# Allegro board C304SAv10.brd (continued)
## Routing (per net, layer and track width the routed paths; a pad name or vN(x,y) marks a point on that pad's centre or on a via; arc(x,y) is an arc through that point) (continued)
27M_FPGA: length 25.1
  TOP w0.15: D9.Y28 v1(34,99) ; R69.2 v1(17.9,108.5)
  BOTTOM w0.15: v1(17.9,108.5) 20.1,106.3 31.9,106.3 34,104.2 v1(34,99)
706MR: length 84
  TOP w0.2: 84.45,56.75 D3.1 82.45,56.75 X3.1 82.45,60.75 R11.1 v3(83.95,61.95) ; D1.74 68.45,105.45 69.95,103.95 v2(70,103.95)
  BOTTOM w0.2: R11.1 v3(83.95,61.95) 83.95,62.95 86.25,65.25 90.05,65.25 90.6,65.8 90.6,71 90.1,71.5 90.1,97.2 83.35,103.95 v2(70,103.95)
706WDI: length 80.7
  TOP w0.2: v2(68.35,104.55) 67.95,104.95 D1.73 ; D3.6 v3(91.71,54.21)
  BOTTOM w0.2: v2(68.35,104.55) 85.95,104.55 92.8,97.7 92.8,55.3 v3(91.71,54.21)
ASI_OUTN1: length 40.8
  TOP w0.2: D9.D1 17.5,70.7 17.4,70.6 17.4,68.4 v2(16.5,67.5) ; v3(8.75,38.1) R76.2
  TOP w0.3: C150.1 8.9,36.65 R76.2
  MIDLAYER w0.2: v3(8.75,38.1) 9.8,39.15 9.8,58.87 16.7,65.77 16.7,67.3 v2(16.5,67.5)
ASI_OUTN2: length 40
  TOP w0.2: D9.G1 20.5,69.61 20.45,69.56 20.45,66.45 v2(19.9,65.9) ; v3(24.75,38.1) R93.2
  TOP w0.3: R93.2 24.9,36.65 C162.1
  MIDLAYER w0.2: v2(19.9,65.9) 20.1,65.9 23.35,62.65 23.35,42.25 25.6,40 25.6,38.95 v3(24.75,38.1)
ASI_OUTN3: length 41.2
  TOP w0.2: D9.W1 32.5,70.86 32.85,70.51 32.85,64.05 v2(32.4,63.6) ; R101.2 40.7,36.85 v3(40.7,38.1)
  TOP w0.3: C170.1 40.9,36.65 R101.2
  MIDLAYER w0.2: v3(40.7,38.1) 41.27,38.67 41.27,38.97 32.7,47.53 32.7,63.3 v2(32.4,63.6)
ASI_OUTN4: length 52.8
  TOP w0.2: D9.AC1 36.5,70.51 36.45,70.46 36.45,67.05 v2(35.9,66.5) ; R109.2 v3(56.75,38.1)
  TOP w0.3: C178.1 56.9,36.65 R109.2
  MIDLAYER w0.2: v2(35.9,66.5) 45.5,66.5 57.75,54.25 57.75,38.3 57.55,38.1 v3(56.75,38.1)
ASI_OUTP1: length 41.8
  TOP w0.2: v3(11.15,38.1) R76.1 ; D9.D2 17,72 17,68.8 v2(16.6,68.4)
  TOP w0.3: C149.1 11,36.65 R76.1
  MIDLAYER w0.2: v3(11.15,38.1) 10.2,39.05 10.2,58.7 17.1,65.6 17.1,67.9 v2(16.6,68.4)
ASI_OUTP2: length 41.3
  TOP w0.2: v2(19.9,66.7) 20.05,66.85 20.05,69.56 20,69.61 20,72 D9.G2 ; v3(27.15,38.1) R93.1
  TOP w0.3: R93.1 27,36.65 C161.1
  MIDLAYER w0.2: v2(19.9,66.7) 23.75,62.85 23.75,42.45 26,40.2 26,39.25 v3(27.15,38.1)
ASI_OUTP3: length 43.1
  TOP w0.2: D9.W2 32,72 32,70.7 32.45,70.25 32.45,64.75 32.3,64.6 v2(32.3,64.5) ; R101.1 43.1,36.85 v3(43.1,38.1)
  TOP w0.3: C169.1 43,36.65 R101.1
  MIDLAYER w0.2: v3(43.1,38.1) 42.7,38.1 33.1,47.7 33.1,63.7 v2(32.3,64.5)
ASI_OUTP4: length 53.8
  TOP w0.2: v2(35.9,67.3) 35.9,67.4 36.05,67.55 36.05,70.46 36,70.51 36,72 D9.AC2 ; R109.1 v3(59.15,38.1)
  TOP w0.3: R109.1 59,36.65 C177.1
  MIDLAYER w0.2: v2(35.9,67.3) 36.3,66.9 45.67,66.9 58.15,54.42 58.15,38.3 58.35,38.1 v3(59.15,38.1)
AT91_CAS: length 54.7
  TOP w0.2: v2(71.9,170.65) D5.17 82.25,170.65 82.75,170.15 82.75,157.25 73.45,147.95 D1.177 ; D6.17 v2(61.35,170.65)
  BOTTOM w0.2: v2(71.9,170.65) v2(61.35,170.65) 61.25,170.65
AT91_NCS0: length 53.4
  TOP w0.2: D1.166 78.95,145.95 v2(79.45,146.45) ; v2(74.8,187.9) 74.8,189.9 74.2,190.5 D7.26 72.85,190.5
  MIDLAYER w0.2: v2(79.45,146.45) 80.25,147.25 80.25,184.35 76.7,187.9 v2(74.8,187.9)
AT91_NCS1: length 51.4
  TOP w0.2: D5.19 v2(78.7,172.25) ; D1.167 78.45,149.55 v2(78.7,149.8) ; D6.19 v2(61.25,172.25)
  BOTTOM w0.2: v2(61.25,172.25) v2(78.7,172.25) 77.3,170.85 77.3,157.1 78.7,155.7 v2(78.7,149.8)
AT91_NCS7: length 64.2
  TOP w0.15: v2(49.5,109.4) 49.5,99.6 46.9,97 41,97 D9.AG26
  TOP w0.2: D1.14 v2(56.85,133.75)
  BOTTOM w0.2: v2(49.5,109.4) 59.9,109.4 64.6,114.1 64.6,131 61.85,133.75 v2(56.85,133.75)
AT91_NRD: length 144.2
  TOP w0.15: v2(51.2,81.6) 51.1,81.5 D9.AH11
  TOP w0.2: D7.28 74.8,191.5 75.5,190.8 v2(75.5,187.1) ; v2(76.95,140.65) D1.170 76.95,145.15 v2(77.2,145.4)
  MIDLAYER w0.2: v2(51.2,81.6) 65.4,81.6 69,85.2 69,100.4 76.1,107.5 76.1,139.8 v2(76.95,140.65) ; v2(77.2,145.4) 79.85,148.05 79.85,183.75 76.5,187.1 v2(75.5,187.1)
AT91_NWE: length 167.4
  TOP w0.15: v2(52.9,82.6) 51.3,82.6 50.7,82 41,82 D9.AG12
  TOP w0.2: D7.11 56.05,196.5 v2(56.15,196.4) ; v2(77.45,146.75) 76.45,145.75 D1.171 76.45,141.35 v2(76.1,141)
  MIDLAYER w0.2: v2(76.1,141) 75.3,140.2 75.3,108 67.6,100.3 67.6,85.2 65,82.6 v2(52.9,82.6) ; v2(56.15,196.4) 56.15,188.65 58.4,186.4 76.2,186.4 79.45,183.15 79.45,148.75 v2(77.45,146.75)
AT91_RAS: length 58.7
  TOP w0.2: v2(72.9,171.45) D5.18 82.35,171.45 83.15,170.65 83.15,156.95 73.95,147.75 D1.176 ; D6.18 v2(58.15,171.45)
  BOTTOM w0.2: v2(58.15,171.45) v2(72.9,171.45)
AT91_SDCKE: length 68
  TOP w0.2: D1.175 74.45,147.4 v2(77.33,150.28) ; v2(73.15,168.45) 70.15,171.45 D5.37 66.75,171.45 62.75,175.45 62.75,178.75 62.05,179.45 56.55,179.45 55.25,178.15 55.25,174.25 52.45,171.45 D6.37
  BOTTOM w0.2: v2(73.15,168.45) 74.75,166.85 74.75,152.85 75.64,151.96 75.65,151.96 ; 77.32,150.28 75.65,151.95 75.65,151.96 ; 75.65,151.96 v2(77.33,150.28)
AT91_SDCLK: length 45.9
  TOP w0.2: D1.174 74.95,146.85 v2(76.15,148.05) ; v2(65.35,167.15) 65.35,168.35 R35.2
  BOTTOM w0.2: v2(76.15,148.05) 65.35,158.85 v2(65.35,167.15) 56.85,167.15 53.35,170.65 R36.2
AT91_SDWE: length 56.6
  TOP w0.2: D1.178 72.95,148.15 82.35,157.55 82.35,169.45 81.95,169.85 D5.16 v2(72.9,169.85) ; D6.16 v2(58.15,169.85)
  BOTTOM w0.2: v2(58.15,169.85) v2(72.9,169.85)
AT91A0: length 48.2
  TOP w0.2: D1.133 v2(88.85,128.75) ; D5.15 v2(81.75,169.05)
  BOTTOM w0.2: v2(88.85,128.75) 89.35,129.25 89.35,161.45 v2(81.75,169.05)
AT91A1: length 204.9
  TOP w0.15: D9.W27 33,98 33,107.9 30.3,110.6 30.3,167 46.6,183.3 v2(55.05,183.3)
  TOP w0.2: v2(71.6,185.5) 71.6,189.6 72,190 D7.25 ; D6.15 v2(61.25,169.05) ; v2(83.55,129.85) 84.15,129.25 D1.134
  MIDLAYER w0.2: v2(61.25,169.05) 59.65,170.65 57.35,170.65 55.05,172.95 v2(55.05,183.3) 55.05,184.85 55.7,185.5 v2(71.6,185.5)
  BOTTOM w0.2: v2(61.25,169.05) 74.55,169.05 76.05,167.55 76.05,154.65 78,152.7 78,135.4 v2(83.55,129.85)
AT91A2: length 218.3
  TOP w0.15: D9.AC27 37,98 37,107 32.3,111.7 32.3,165.8 46.15,179.65 v2(50.35,179.65)
  TOP w0.2: D5.23 v2(81.75,175.45) ; D6.23 v2(61.25,175.45) ; D7.24 54.9,190 55.65,189.25 v2(55.65,184.35) ; v2(89.15,180.54) 89.55,180.14 89.55,150.91 92.75,147.71 92.75,133.05 89.45,129.75 D1.135
  MIDLAYER w0.2: v2(55.65,184.35) 55.65,176.55 56.75,175.45 v2(61.25,175.45)
  BOTTOM w0.2: v2(50.35,179.65) 51.85,179.65 56.05,175.45 v2(61.25,175.45) v2(81.75,175.45) 84.05,175.45 89.14,180.54 v2(89.15,180.54)
AT91A3: length 213.3
  TOP w0.15: D9.AC28 36.5,106.8 31.8,111.5 31.8,166.1 46.05,180.35 v2(48.85,180.35)
  TOP w0.2: v2(56.25,183.25) 56.25,189.55 55.3,190.5 D7.23 ; D1.136 89.35,130.25 92.35,133.25 92.35,147.54 89.15,150.74 89.15,179.65 87.95,180.85 v2(87.93,180.85) ; D6.24 v2(58.15,176.25) ; D5.24 v2(78.65,176.25)
  MIDLAYER w0.2: v2(58.15,176.25) 57.05,176.25 56.25,177.05 v2(56.25,183.25)
  BOTTOM w0.2: v2(87.93,180.85) 87.93,180.83 83.35,176.25 v2(78.65,176.25) v2(58.15,176.25) 55.98,176.25 51.88,180.35 v2(48.85,180.35)
AT91A4: length 216.9
  TOP w0.15: D9.AB27 36,98 36,106.6 31.3,111.3 31.3,166.4 45.98,181.08 v2(50.3,181.08)
  TOP w0.2: D6.25 v2(61.25,177.05) ; D1.137 89.25,130.75 91.95,133.45 91.95,147.38 88.75,150.58 88.75,179.18 v2(86.76,181.16) ; v2(57.45,184.25) 57.45,189.25 55.7,191 D7.22 ; D5.25 v2(81.75,177.05)
  MIDLAYER w0.2: v2(57.45,184.25) 57.45,177.25 57.65,177.05 v2(61.25,177.05)
  BOTTOM w0.2: v2(50.3,181.08) 51.72,181.08 56.15,176.65 57.55,176.65 57.95,177.05 v2(61.25,177.05) v2(81.75,177.05) 82.65,177.05 v2(86.76,181.16)
AT91A5: length 212
  TOP w0.15: D9.AB28 35.5,106.4 30.8,111.1 30.8,166.7 45.82,181.72 v2(48.92,181.72)
  TOP w0.2: D5.26 v2(78.65,177.85) ; D1.138 89.15,131.25 91.55,133.65 91.55,147.21 88.35,150.41 88.35,178.73 v2(85.54,181.54) ; v2(58.15,183.25) 58.15,189.45 56.1,191.5 D7.21 ; D6.26 v2(58.15,177.85)
  MIDLAYER w0.2: v2(58.15,177.85) v2(58.15,183.25)
  BOTTOM w0.2: v2(48.92,181.72) 51.88,181.72 56.35,177.25 57.55,177.25 v2(58.15,177.85) v2(78.65,177.85) 81.85,177.85 v2(85.54,181.54)
AT91A6: length 212.1
  TOP w0.15: v2(46.05,177.85) 45.99,177.91 45.21,177.91 32.8,165.5 32.8,111.9 37.5,107.2 D9.AD28
  TOP w0.2: D1.139 89.05,131.75 91.15,133.85 91.15,147.04 87.95,150.24 87.95,178.28 83.58,182.65 75.35,182.65 70.55,177.85 D5.29 67.05,177.85 66.65,178.25 66.65,181.25 65.25,182.65 52.85,182.65 51.25,181.05 51.25,178.75 50.35,177.85 D6.29 v2(46.05,177.85) ; 53.65,192 D7.20 48.9,192 46.05,189.15 v2(46.05,184.25)
  MIDLAYER w0.2: v2(46.05,177.85) v2(46.05,184.25)
AT91A7: length 214.6
  TOP w0.15: D9.AD27 38,98 38,108 33.3,112.7 33.3,165.2 45.15,177.05 v2(46.85,177.05)
  TOP w0.2: D1.140 88.95,132.25 90.75,134.05 90.75,146.88 87.55,150.08 87.55,178.11 83.41,182.25 75.75,182.25 70.55,177.05 D5.30 66.75,177.05 66.15,177.65 66.15,181.05 64.95,182.25 53.25,182.25 51.75,180.75 51.75,178.35 50.45,177.05 D6.30 v2(46.85,177.05) ; v2(45.45,185.25) 45.45,189.35 48.6,192.5 D7.19 53.65,192.5
  MIDLAYER w0.2: v2(45.45,185.25) 45.45,177.45 45.85,177.05 v2(46.85,177.05)
AT91A8: length 212.7
  TOP w0.15: D9.AE28 38.5,108.2 33.8,112.9 33.8,164.9 45.15,176.25 v2(45.95,176.25)
  TOP w0.2: v2(45.95,176.25) D6.31 50.65,176.25 52.25,177.85 52.25,180.45 53.65,181.85 64.65,181.85 65.65,180.85 65.65,177.25 66.65,176.25 D5.31 70.55,176.25 76.15,181.85 83.25,181.85 87.15,177.95 87.15,149.91 90.35,146.71 90.35,134.25 88.85,132.75 D1.141 ; v2(44.85,184.25) 44.85,189.55 48.3,193 D7.18
  MIDLAYER w0.2: v2(44.85,184.25) 44.85,177.35 v2(45.95,176.25)
AT91A9: length 216.8
  TOP w0.15: v2(46.75,175.45) 45.15,175.45 34.3,164.6 34.3,113.1 39,108.4 39,98 D9.AE27
  TOP w0.2: D7.8 52.5,198 44.25,189.75 v2(44.25,185.35) ; D1.142 88.75,133.25 89.95,134.45 89.95,146.55 86.75,149.75 86.75,177.78 83.08,181.45 76.55,181.45 70.55,175.45 D5.32 66.65,175.45 65.15,176.95 65.15,180.55 64.25,181.45 54.05,181.45 52.75,180.15 52.75,177.35 50.85,175.45 D6.32 v2(46.75,175.45)
  MIDLAYER w0.2: v2(46.75,175.45) 45.85,175.45 44.25,177.05 v2(44.25,185.35)
AT91A10: length 219.7
  TOP w0.15: v1(39.5,99.2) 39.5,108.6 34.7,113.4 34.7,164.1 45.25,174.65 v2(45.85,174.65) ; D9.AD24 v1(38,95)
  TOP w0.2: v2(45.85,174.65) D6.33 51.15,174.65 53.25,176.75 53.25,179.75 54.55,181.05 63.75,181.05 64.65,180.15 64.65,176.65 66.65,174.65 D5.33 70.55,174.65 76.95,181.05 82.91,181.05 86.35,177.61 86.35,149.58 89.55,146.38 89.55,134.65 88.65,133.75 D1.143 ; D7.7 52.2,198.5 43.65,189.95 v2(43.65,184.25)
  MIDLAYER w0.15: v1(38,95) 39.5,96.5 v1(39.5,99.2)
  MIDLAYER w0.2: v2(45.85,174.65) 43.65,176.85 v2(43.65,184.25)
AT91A11: length 132
  TOP w0.2: v2(46.65,173.85) D6.34 51.35,173.85 53.75,176.25 53.75,179.35 55.05,180.65 63.25,180.65 64.15,179.75 64.15,176.35 66.65,173.85 D5.34 70.55,173.85 77.35,180.65 82.75,180.65 85.95,177.45 85.95,149.41 89.15,146.21 89.15,135.95 87.95,134.75 D1.145 ; v2(43.05,185.35) 43.05,190.15 51.9,199 D7.6
  MIDLAYER w0.2: v2(46.65,173.85) 45.75,173.85 43.05,176.55 v2(43.05,185.35)
AT91A12: length 89.6
  TOP w0.2: v2(83.05,136.95) 83.75,136.25 D1.148 ; D7.5 57.7,199.5 v2(60.05,197.15)
  MIDLAYER w0.2: v2(83.05,136.95) 83.05,138.75 84.85,140.55 84.85,147.35 84.35,147.85 84.35,186.35 73.55,197.15 v2(60.05,197.15)
AT91A13: length 131.7
  TOP w0.2: D7.4 52.1,200 42.45,190.35 v2(42.45,184.25) ; v2(45.85,173.05) D6.35 51.65,173.05 54.25,175.65 54.25,178.95 55.55,180.25 62.65,180.25 63.75,179.15 63.75,175.95 66.65,173.05 D5.35 70.55,173.05 77.75,180.25 82.58,180.25 85.55,177.28 85.55,149.25 88.75,146.05 88.75,137.78 87.72,136.75 D1.149
  MIDLAYER w0.2: v2(42.45,184.25) 42.45,176.45 v2(45.85,173.05)
AT91A14: length 133.1
  TOP w0.2: v2(41.85,185.35) 41.85,190.55 51.8,200.5 D7.3 ; D1.150 87.65,137.25 88.35,137.95 88.35,145.88 85.15,149.08 85.15,177.12 82.42,179.85 78.15,179.85 70.55,172.25 D5.36 66.65,172.25 63.25,175.65 63.25,178.95 62.35,179.85 56.05,179.85 54.75,178.55 54.75,174.95 52.05,172.25 D6.36 v2(46.65,172.25)
  MIDLAYER w0.2: v2(46.65,172.25) 45.65,172.25 41.85,176.05 v2(41.85,185.35)
AT91A15: length 87.9
  TOP w0.2: v2(61.75,196.45) 57.2,201 D7.2 ; D1.151 84.95,137.75 84.85,137.65 83.75,137.65 83.05,138.35 v2(83.05,139.95)
  MIDLAYER w0.2: v2(61.75,196.45) 73.35,196.45 83.85,185.95 83.85,147.65 84.25,147.25 84.25,141.15 v2(83.05,139.95)
AT91A16: length 116.1
  TOP w0.2: D7.1 57.7,201.5 62.35,196.85 v2(62.35,184.25) ; D6.20 v2(58.15,173.05) ; D1.154 87.25,139.25 87.95,139.95 87.95,145.72 84.75,148.92 84.75,176.95 82.25,179.45 78.57,179.45 77.9,178.78 77.9,173.85 v2(78.7,173.05) D5.20
  MIDLAYER w0.2: v2(62.35,184.25) 62.35,175.05 61.95,174.65 59.75,174.65 v2(58.15,173.05)
  BOTTOM w0.2: v2(58.15,173.05) v2(78.7,173.05)
AT91A17: length 97.7
  TOP w0.2: D5.21 v2(81.75,173.85) 83.95,171.65 83.95,147.95 87.55,144.35 87.55,140.28 87.02,139.75 D1.155 ; v2(63.05,183.25) 63.05,197 67.55,201.5 D7.48 ; D6.21 v2(61.25,173.85)
  MIDLAYER w0.2: v2(61.25,173.85) 62.05,173.85 63.05,174.85 v2(63.05,183.25)
  BOTTOM w0.2: v2(61.25,173.85) v2(81.75,173.85)
AT91A18: length 88.2
  TOP w0.2: D1.156 86.95,140.25 87.15,140.45 87.15,143.65 v2(86.25,144.55) ; D7.17 57.6,193.5 v2(57.7,193.4)
  MIDLAYER w0.2: v2(57.7,193.4) 57.7,196.6 58.85,197.75 73.85,197.75 84.85,186.75 84.85,148.35 85.45,147.75 85.45,145.35 v2(86.25,144.55)
AT91A19: length 77.2
  TOP w0.2: D1.157 v2(83.45,147.05) ; D7.16 58.1,194 v2(58.35,194.25)
  MIDLAYER w0.2: v2(58.35,194.25) 59.35,195.25 73.65,195.25 83.35,185.55 83.35,147.15 v2(83.45,147.05)
AT91A20: length 77.3
  TOP w0.2: D7.9 58.75,197.5 v2(61.6,194.65) ; v2(82.35,146.45) 82.95,145.85 D1.158
  MIDLAYER w0.2: v2(61.6,194.65) 67.75,194.65 70.85,191.55 76.45,191.55 82.85,185.15 82.85,146.95 v2(82.35,146.45)
AT91A21: length 76
  TOP w0.2: D1.159 82.45,144.62 v2(81.83,145.25) ; D7.10 57.5,197 v2(60.4,194.1)
  MIDLAYER w0.2: v2(60.4,194.1) 65.4,194.1 70.15,189.35 77.75,189.35 81.05,186.05 81.05,146.03 v2(81.83,145.25)
AT91A22: length 74.6
  TOP w0.2: v2(61.65,193.5) 60.1,193.5 58.1,195.5 D7.13 ; D1.160 81.95,144.25 v2(80.65,145.55)
  MIDLAYER w0.2: v2(80.65,145.55) 80.65,185.55 77.45,188.75 69.85,188.75 65.1,193.5 v2(61.65,193.5)
AT91D0: length 138.4
  TOP w0.15: D9.AH12 48.1,82.5 v2(53.2,87.6)
  TOP w0.2: v2(73.75,181.95) 73.75,184.52 76.35,187.12 76.35,190.95 75.3,192 D7.29 ; v2(72.45,140.6) D1.179 72.45,148.35 78.35,154.25 78.35,158.25 v2(78.75,158.65) D5.2
  MIDLAYER w0.2: v2(73.75,181.95) 73.75,162.85 77.95,158.65 v2(78.75,158.65) ; v2(72.45,140.6) 72.7,140.35 72.7,137.5 68.4,133.2 68.4,110.2 63.1,104.9 63.1,97.6 59.4,93.9 59.4,91.1 57.5,89.2 54.8,89.2 v2(53.2,87.6)
  BOTTOM w0.2: 73.75,181.9 v2(73.75,181.95)
AT91D1: length 136.5
  TOP w0.15: v2(53.4,88.7) 51.7,87 41,87 D9.AG17
  TOP w0.2: v2(72.1,139.5) 71.8,139.8 71.8,141.55 71.95,141.7 D1.180 71.95,148.55 77.85,154.45 77.85,159.4 v2(77.98,159.53) 77.98,159.58 78.65,160.25 D5.4 ; v2(74.35,182.95) 74.35,184.55 76.85,187.05 76.85,191.45 75.3,193 D7.31
  MIDLAYER w0.2: v2(74.35,182.95) 74.35,163.15 v2(77.98,159.53) ; v2(72.1,139.5) 72.1,137.7 67.9,133.5 67.9,110.5 62.6,105.2 62.6,97.9 v2(53.4,88.7)
AT91D2: length 135.4
  TOP w0.15: D9.AH17 51.4,87.5 v2(52.3,88.4)
  TOP w0.2: D5.5 78.55,161.05 v2(78.25,160.75) 77.35,159.85 77.35,154.65 71.45,148.75 D1.181 v2(71.45,138.6) ; v2(74.95,184.25) 74.95,184.52 77.45,187.02 77.45,191.85 75.3,194 D7.33 72.85,194
  MIDLAYER w0.2: v2(52.3,88.4) 62.1,98.2 62.1,105.5 67.4,110.8 67.4,133.8 71.5,137.9 71.5,138.45 71.45,138.5 v2(71.45,138.6) ; v2(74.95,184.25) 74.95,164.05 v2(78.25,160.75)
AT91D3: length 138.1
  TOP w0.15: D9.AF18 40,88 51.1,88 v2(52.6,89.5)
  TOP w0.2: 72.85,195 D7.35 75.3,195 78.05,192.25 78.05,187.05 75.55,184.55 v2(75.55,183.25) ; D5.7 78.75,162.65 v2(78.25,162.15) 76.85,160.75 76.85,154.85 70.95,148.95 D1.182 70.95,141.7 71.1,141.55 71.1,139.9 v2(70.7,139.5)
  MIDLAYER w0.2: v2(52.6,89.5) 61.6,98.5 61.6,105.8 66.9,111.1 66.9,134.1 70.3,137.5 70.3,139.1 v2(70.7,139.5) ; v2(78.25,162.15) 75.55,164.85 v2(75.55,183.25)
AT91D4: length 136.2
  TOP w0.15: v2(51.4,89.1) 50.8,88.5 D9.AH18
  TOP w0.2: D7.38 75.1,196.5 78.55,193.05 78.55,186.92 76.15,184.52 v2(76.15,184.25) ; v2(69.8,140.35) 69.7,140.35 69.45,140.6 D1.185 69.45,148.15 76.35,155.05 76.35,161.15 v2(78.65,163.45) D5.8
  MIDLAYER w0.2: v2(76.15,184.25) 76.15,165.95 v2(78.65,163.45) ; v2(51.4,89.1) 61.1,98.8 61.1,106.1 66.4,111.4 66.4,134.4 69.8,137.8 v2(69.8,140.35)
AT91D5: length 137.5
  TOP w0.15: v2(51.7,90.2) 50.5,89 41,89 D9.AG18
  TOP w0.2: D7.40 75.1,197.5 79.05,193.55 79.05,186.85 76.75,184.55 v2(76.75,183.25) ; v2(68.8,139.2) 68.8,139.25 68.95,139.4 D1.186 68.95,148.35 75.85,155.25 75.85,162.15 v2(78.35,164.65) 78.75,165.05 D5.10
  MIDLAYER w0.2: v2(78.35,164.65) 76.75,166.25 v2(76.75,183.25) ; v2(51.7,90.2) 56.4,94.9 56.4,102.2 65.9,111.7 65.9,134.7 68.8,137.6 v2(68.8,139.2)
AT91D6: length 134.3
  TOP w0.15: v2(52,98.2) 47.8,94 41,94 D9.AG23
  TOP w0.2: D5.11 v2(78.35,165.85) 75.35,162.85 75.35,155.45 68.45,148.55 D1.187 68.45,141.7 68.5,141.65 68.5,141 67.7,140.2 v2(67.6,140.2) ; v2(77.35,184.25) 79.55,186.45 79.55,193.95 75,198.5 D7.42
  MIDLAYER w0.2: v2(78.35,165.85) 77.35,166.85 v2(77.35,184.25) ; v2(67.6,140.2) 63.3,140.2 62,138.9 62,137.2 59.8,135 59.8,120.6 52.4,113.2 52.4,98.6 v2(52,98.2)
AT91D7: length 136.3
  TOP w0.15: v2(52.8,97.4) 48.4,93 41,93 D9.AG22
  TOP w0.2: v2(77.95,183.25) 80.15,185.45 80.15,194.25 74.92,199.47 73.12,199.47 D7.44 ; D5.13 v2(78.15,167.45) 74.85,164.15 74.85,155.65 66.95,147.75 D1.190 66.95,139.55 v2(67.3,139.2)
  MIDLAYER w0.2: v2(78.15,167.45) 77.95,167.65 v2(77.95,183.25) ; v2(67.3,139.2) 63.9,139.2 63,138.3 63,136.6 60.8,134.4 60.8,120 53.4,112.6 53.4,98 v2(52.8,97.4)
AT91D8: length 128.2
  TOP w0.15: D9.AH19 48.9,89.5 v2(53.15,93.75)
  TOP w0.2: v2(68.2,138.3) 68,138.5 67.1,138.5 66.45,139.15 D1.191 66.45,147.95 74.25,155.75 74.25,164.55 v2(71.35,167.45) D5.42 ; v2(70.95,184.75) 70.95,191.35 72.1,192.5 D7.30
  MIDLAYER w0.2: v2(70.95,184.75) 70.95,167.85 v2(71.35,167.45) ; v2(68.2,138.3) 68.2,137.8 65.4,135 65.4,112 55.9,102.5 55.9,96.5 v2(53.15,93.75)
AT91D9: length 129.5
  TOP w0.15: v2(53.4,94.8) 48.6,90 41,90 D9.AG19
  TOP w0.2: v2(67,137.9) 65.95,138.95 D1.192 65.95,148.15 73.75,155.95 73.75,164.15 v2(72.05,165.85) D5.44 ; v2(70.35,183.25) 70.35,191.85 72,193.5 D7.32
  MIDLAYER w0.2: v2(67,137.9) 67,137.4 64.9,135.3 64.9,112.3 55.4,102.8 55.4,96.8 v2(53.4,94.8) ; v2(72.05,165.85) 70.35,167.55 v2(70.35,183.25)
AT91D10: length 127.3
  TOP w0.15: D9.AH21 49.3,91.5 v2(52.3,94.5)
  TOP w0.2: v2(69.75,184.75) 69.75,192.25 72,194.5 D7.34 ; D5.45 v2(71.55,165.05) 73.25,163.35 73.25,156.15 65.45,148.35 D1.193 65.45,138.15 v2(65.9,137.7)
  MIDLAYER w0.2: v2(69.75,184.75) 69.75,166.85 v2(71.55,165.05) ; v2(65.9,137.7) 65.9,137.1 64.4,135.6 64.4,113.9 54.9,104.4 54.9,97.1 v2(52.3,94.5)
AT91D11: length 128.6
  TOP w0.15: v2(52.6,95.6) 49,92 41,92 D9.AG21
  TOP w0.2: v2(64.7,137.6) 64.7,139.8 64.95,140.05 D1.194 64.95,148.55 72.75,156.35 72.75,162.35 v2(71.65,163.45) D5.47 ; D7.36 72,195.5 69.15,192.65 v2(69.15,183.25)
  MIDLAYER w0.2: v2(52.6,95.6) 54.4,97.4 54.4,104.7 63.9,114.2 63.9,135.9 64.7,136.7 v2(64.7,137.6) ; v2(71.65,163.45) 69.15,165.95 v2(69.15,183.25)
AT91D12: length 129.1
  TOP w0.15: v2(51.5,95.3) 48.7,92.5 D9.AH22
  TOP w0.2: v2(63.6,138.1) 63.6,139.5 64.45,140.35 D1.195 64.45,148.75 72.25,156.55 72.25,161.55 v2(71.15,162.65) D5.48 ; v2(68.55,184.75) 68.55,195.75 69.8,197 D7.39
  MIDLAYER w0.2: v2(51.5,95.3) 53.9,97.7 53.9,112.3 61.3,119.7 61.3,126.2 62.5,127.4 62.5,135.3 63.6,136.4 v2(63.6,138.1) ; v2(71.15,162.65) 68.55,165.25 v2(68.55,184.75)
AT91D13: length 128.8
  TOP w0.15: v2(51.7,97.1) 48.1,93.5 D9.AH23
  TOP w0.2: v2(67.95,183.25) 67.95,196.15 69.6,197.8 71.7,197.8 71.9,198 D7.41 ; v2(62.6,138.7) 62.6,139.2 63.95,140.55 D1.196 63.95,148.95 71.75,156.75 71.75,160.45 v2(71.15,161.05) D5.50
  MIDLAYER w0.2: v2(71.15,161.05) 67.95,164.25 v2(67.95,183.25) ; v2(51.7,97.1) 52.9,98.3 52.9,112.9 60.3,120.3 60.3,134.7 62.5,136.9 62.5,138.6 v2(62.6,138.7)
AT91D14: length 128.9
  TOP w0.15: v2(50.9,97.9) 48.5,95.5 D9.AH25
  TOP w0.2: D7.43 69.8,199 67.25,196.45 67.25,191.95 66.55,191.25 v2(66.55,184.75) ; D5.51 70.35,160.25 v2(70.85,159.75) 71.25,159.35 71.25,156.95 63.45,149.15 D1.197 63.45,140.75 62.3,139.6 v2(61.9,139.6)
  MIDLAYER w0.2: v2(70.85,159.75) 66.55,164.05 v2(66.55,184.75) ; v2(50.9,97.9) 51.9,98.9 51.9,113.5 59.3,120.9 59.3,137 v2(61.9,139.6)
AT91D15: length 131.1
  TOP w0.15: D9.AG25 41,96 48.1,96 v2(51.1,99)
  TOP w0.2: v2(65.95,183.25) 65.95,191.65 66.65,192.35 66.65,196.85 69.8,200 D7.45 ; v2(61.5,140.7) 62.7,140.7 63.1,141.1 63.1,141.55 62.95,141.7 D1.198 62.95,149.35 70.75,157.15 70.75,158.15 70.25,158.65 D5.53 66.55,158.65 v2(65.95,159.25)
  MIDLAYER w0.2: v2(65.95,159.25) v2(65.95,183.25) ; v2(61.5,140.7) 58.8,138 58.8,121.2 51.4,113.8 51.4,99.3 v2(51.1,99)
AT91D16: length 19.1
  TOP w0.2: D1.201 61.45,146.55 57.85,150.15 57.85,158.15 58.35,158.65 D6.2
AT91D17: length 20.9
  TOP w0.2: D1.202 60.95,146.25 57.35,149.85 57.35,159.35 58.25,160.25 D6.4
AT91D18: length 22
  TOP w0.2: D1.203 60.45,145.85 56.85,149.45 56.85,159.75 58.15,161.05 D6.5
AT91D19: length 23.8
  TOP w0.2: D6.7 58.25,162.65 56.35,160.75 56.35,149.05 59.95,145.45 D1.204
AT91D20: length 24.8
  TOP w0.2: D6.8 58.25,163.45 55.85,161.05 55.85,148.75 59.45,145.15 D1.205
AT91D21: length 26.6
  TOP w0.2: D6.10 58.25,165.05 55.35,162.15 55.35,148.45 58.95,144.85 D1.206
AT91D22: length 27.6
  TOP w0.2: D1.207 58.45,144.75 54.85,148.35 54.85,162.55 58.15,165.85 D6.11
AT91D23: length 29.4
  TOP w0.2: D6.13 58.15,167.45 54.35,163.65 54.35,148.05 57.95,144.45 D1.208
AT91D24: length 31.9
  TOP w0.2: D6.42 49.95,167.45 53.75,163.65 53.75,140.65 54.15,140.25 D1.1
AT91D25: length 30.9
  TOP w0.2: D1.2 53.95,139.75 53.25,140.45 53.25,162.55 49.95,165.85 D6.44
AT91D26: length 30.8
  TOP w0.2: D6.45 49.85,165.05 52.75,162.15 52.75,140.15 53.65,139.25 D1.3
AT91D27: length 29.9
  TOP w0.2: D6.47 49.95,163.45 52.25,161.15 52.25,139.85 53.35,138.75 D1.4
AT91D28: length 29.7
  TOP w0.2: D1.5 53.05,138.25 51.75,139.55 51.75,160.75 49.85,162.65 D6.48
AT91D29: length 28.9
  TOP w0.2: D1.6 52.71,137.75 51.25,139.21 51.25,159.75 49.95,161.05 D6.50
AT91D30: length 29.1
  TOP w0.2: D1.9 53.35,136.25 50.75,138.85 50.75,159.35 49.85,160.25 D6.51
AT91D31: length 28.2
  TOP w0.2: D1.10 52.95,135.75 50.25,138.45 50.25,158.15 49.75,158.65 D6.53
AT91NBS1: length 31.6
  TOP w0.2: v2(77,149.1) 77,147.2 75.95,146.15 D1.172 ; D5.39 69.95,169.85 v2(72.55,167.25)
  BOTTOM w0.2: v2(77,149.1) 73.85,152.25 73.85,165.95 v2(72.55,167.25)
AT91NBS3: length 45.5
  TOP w0.2: v2(55.35,167.35) 52.85,169.85 D6.39 ; D1.173 75.45,146.5 v2(75.78,146.83)
  BOTTOM w0.2: v2(55.35,167.35) 55.35,160.05 58.65,156.75 65.85,156.75 v2(75.78,146.83)
AT91NRST: length 76.9
  TOP w0.2: D3.7 91.98,55.48 95.1,58.6 95.1,69.5 90.1,74.5 90.1,81.95 X5.12 92.9,84.75 92.9,98.6 91.3,100.2 v3(91.3,116.3) ; v2(88.05,119.9) 87.9,119.75 D1.115
  BOTTOM w0.2: v2(88.05,119.9) 89.2,119.9 R9.2 C2.1 v3(91.3,116.3)
AT91NTRST: length 31.4
  TOP w0.2: X5.3 90.1,94.65 90.1,97.2 87.95,99.35 87.95,111.05 89.85,112.95 89.85,116.25 88.85,117.25 D1.110
  BOTTOM w0.2: X5.3 86.97,93.33 R29.1
AT91SDA10: length 71.4
  TOP w0.2: D6.22 v2(58.15,174.65) ; v2(78.65,174.65) D5.22 82.45,174.65 84.35,172.75 84.35,148.45 v2(87.25,145.55) ; D1.144 88.3,134.25 v2(88.61,134.56)
  BOTTOM w0.2: v2(87.25,145.55) 88.61,144.19 v2(88.61,134.56) ; v2(78.65,174.65) v2(58.15,174.65)
AT91TCK: length 36.7
  TOP w0.2: D1.108 88.15,116.25 88.85,115.55 88.85,113.35 86.75,111.25 86.75,87.74 X5.9
  BOTTOM w0.2: X5.9 86.99,85.71 R32.1
AT91TDI: length 29.6
  TOP w0.2: D1.106 87.25,115.25 87.85,114.65 87.85,113.75 85.55,111.45 v2(85.55,92.05)
  BOTTOM w0.2: v2(85.55,92.05) 86.8,90.8 R30.1 86.96,90.79 X5.5
AT91TDO: length 40.3
  TOP w0.2: D1.107 87.45,115.75 88.35,114.85 88.35,113.55 86.15,111.35 86.15,85.8 X5.11
  BOTTOM w0.2: R34.1 86.98,83.17 X5.11 88.76,83.15 86.85,83.15
AT91TMS: length 34.7
  TOP w0.2: X5.7 87.35,89.68 87.35,111.15 89.35,113.15 89.35,115.85 88.45,116.75 D1.109
  BOTTOM w0.2: X5.7 R31.1
BOARDDET_0: length 6.1
  BOTTOM w0.15: X1.A32 89.34,214 92.2,214 93.2,213 R1.1
BOARDDET_1: length 2.2
  BOTTOM w0.15: R2.1 88.9,211.9 X1.B32
BOARDDET_2: length 2.2
  BOTTOM w0.15: X1.C32 88.8,209.38 R3.1
E3.3VA: length 13.5
  TOP w0.3: D8.36 v2(70.25,85.35) ; v2(70.45,90.95) 70.55,91.05 D8.48
  BOTTOM w0.3: 71.83,86.35 70.83,85.35 v2(70.25,85.35) ; v2(70.45,90.95) 70.95,90.95 71.55,90.35 C77.1 C76.1 71.55,86.63 C75.1
  BOTTOM w0.5: 71.83,86.35 71.83,86.35 C75.1 71.83,84.55 71.83,84.55 71.83,82.95 L2.2
ENETCOL: length 27.4
  TOP w0.2: 81.45,112.4 D1.100 81.45,103.95 77,99.5 72.1,99.5 71,98.4 71,96.8 70.25,96.05 D8.1
ENETCRS: length 30.5
  TOP w0.2: 57.95,112.4 D1.53 v2(57.95,102.25) ; D8.23 60.5,86.05 57.55,89 v2(57.55,91.9)
  BOTTOM w0.2: v2(57.55,91.9) 57.55,101.85 v2(57.95,102.25)
ENETMDC: length 38.8
  TOP w0.2: v2(60.5,104.4) 60.95,104.85 D1.59 60.95,112.4 ; v2(56.35,88.55) 62,82.9 64.5,82.9 64.75,83.15 D8.25
  BOTTOM w0.2: v2(60.5,104.4) 59.95,103.85 57.7,103.85 56.35,102.5 v2(56.35,88.55)
ENETMDIO: length 42.3
  TOP w0.2: 61.45,112.4 D1.60 61.45,104.3 60.31,103.16 v2(59.55,103.16) ; v2(56.95,85.8) 60.95,81.8 63.8,81.8 64,81.6 R8.2 65.25,81.75 D8.26
  BOTTOM w0.2: v2(56.95,85.8) 56.95,102.3 57.81,103.16 v2(59.55,103.16)
ENETRX0: length 29
  TOP w0.2: v2(58.15,90.9) 58.15,90.1 61.2,87.05 D8.21 ; 58.45,112.4 D1.54 58.45,102.7 58.65,102.5 v2(58.65,101.35)
  BOTTOM w0.2: v2(58.65,101.35) 58.15,100.85 v2(58.15,90.9)
ENETRX1: length 28.1
  TOP w0.2: D8.20 61.55,87.55 58.75,90.35 v2(58.75,91.9) ; v2(59.35,100.45) 59.35,102.53 58.95,102.92 D1.55 58.95,112.4
  BOTTOM w0.2: v2(58.75,91.9) 58.75,99.85 v2(59.35,100.45)
ENETRX2: length 41.3
  TOP w0.2: 79.95,112.4 D1.97 79.95,105.65 v2(75.8,101.5) ; D8.19 61.95,88.05 59.95,90.05 v2(59.95,91.9)
  BOTTOM w0.2: v2(75.8,101.5) 64.7,101.5 59.95,96.75 v2(59.95,91.9)
ENETRX3: length 40.7
  TOP w0.2: D8.18 62.15,88.55 60.55,90.15 v2(60.55,90.9) ; 80.45,112.4 D1.98 80.45,104.75 v2(77.15,101.45)
  BOTTOM w0.2: v2(77.15,101.45) 76.6,100.9 65,100.9 60.55,96.45 v2(60.55,90.9)
ENETRX+: length 63.5
  TOP w0.2: v2(68.7,72.3) 68.2,72.8 68.2,80.8 67.7,81.3 67.7,82.66 67.75,82.71 D8.31
  TOP w0.3: T1.6 v3(74.85,27.4)
  MIDLAYER w0.2: v3(74.85,27.4) 73.98,27.4 73.78,27.6 73.78,31.47 68.25,37 68.25,71.85 v2(68.7,72.3)
  BOTTOM w0.2: v3(74.85,27.4) 74.9,27.45 R55.2
ENETRX-: length 63.5
  TOP w0.2: D8.30 67.25,82.71 67.3,82.66 67.3,81.13 67.8,80.63 67.8,72.7 v2(67.4,72.3)
  TOP w0.3: T1.8 v3(72.31,27.4)
  MIDLAYER w0.2: v2(67.4,72.3) 67.85,71.85 67.85,36.83 73.38,31.3 73.38,27.6 73.18,27.4 v3(72.31,27.4)
  BOTTOM w0.2: R52.2 72.3,27.41 v3(72.31,27.4)
ENETRXCK: length 40.6
  TOP w0.2: v2(61.15,91.9) 61.15,90.35 61.95,89.55 D8.16 ; v2(79.9,101.4) 81.95,103.45 D1.101 81.95,112.4
  BOTTOM w0.2: v2(61.15,91.9) 61.15,95.45 65.3,99.6 78.1,99.6 v2(79.9,101.4)
ENETRXDV: length 46.2
  TOP w0.2: D8.22 60.8,86.55 59.65,87.71 v2(59.33,88.03) ; 80.95,112.4 D1.99 80.95,104.35 v2(78.7,102.1)
  BOTTOM w0.2: v2(59.33,88.03) 59.33,88.08 59.35,88.1 59.35,97.05 64.4,102.1 v2(78.7,102.1)
ENETRXER: length 36.1
  TOP w0.2: R140.2 55.4,89.7 v2(55.75,90.05) 60.25,85.55 D8.24 ; v2(59.55,104.55) 60.45,105.45 D1.58 60.45,112.4
  BOTTOM w0.2: v2(55.75,90.05) 55.75,102.8 57.5,104.55 v2(59.55,104.55)
ENETTX0: length 34.1
  TOP w0.2: D1.51 54.25,115.25 53.65,114.65 53.65,102.48 58.33,97.8 65.1,97.8 67.75,95.15 D8.6
ENETTX1: length 33.5
  TOP w0.2: D1.52 54.45,114.75 54.05,114.35 54.05,102.85 58.5,98.4 65.6,98.4 68.25,95.75 D8.5
ENETTX2: length 24.4
  TOP w0.2: 77.45,112.4 D1.92 77.45,105.15 73.5,101.2 71.9,101.2 68.75,98.05 D8.4
ENETTX3: length 24.9
  TOP w0.2: D8.3 69.25,97.65 72.1,100.5 73.8,100.5 78.95,105.65 D1.95 78.95,112.4
ENETTX+: length 65.5
  TOP w0.2: v2(71.8,72.4) 71.4,72.8 71.4,79.8 69.2,82 69.2,82.66 69.25,82.71 D8.34
  TOP w0.3: T1.1 v3(81.2,27.4)
  MIDLAYER w0.2: v3(81.2,27.4) 80.33,27.4 80.13,27.6 80.13,31.27 71.4,40 71.4,72 v2(71.8,72.4)
  BOTTOM w0.2: R57.2 v3(81.2,27.4)
ENETTX-: length 65.5
  TOP w0.2: D8.33 68.75,82.71 68.8,82.66 68.8,81.83 71,79.63 71,72.8 v2(70.6,72.4)
  TOP w0.3: T1.3 v3(78.66,27.4)
  MIDLAYER w0.2: v3(78.66,27.4) 79.53,27.4 79.73,27.6 79.73,31.1 71,39.83 71,72 v2(70.6,72.4)
  BOTTOM w0.2: R56.2 78.7,27.44 v3(78.66,27.4)
ENETTXCK: length 36.6
  TOP w0.2: D1.49 53.45,116.25 52.65,115.45 52.65,101.55 57.7,96.5 65.2,96.5 67.25,94.45 D8.7
ENETTXEN: length 38.7
  TOP w0.2: D1.50 54.05,115.75 53.25,114.95 53.25,102.05 58.2,97.1 v2(64.7,97.1) ; D8.2 69.75,96.45 v2(69.95,96.65)
  BOTTOM w0.2: v2(64.7,97.1) 69.5,97.1 v2(69.95,96.65)
F_LED0: length 21.6
  TOP w0.15: D9.AB23 v1(36,94) ; v1(40.2,110.8) HL10.2
  MIDLAYER w0.15: v1(40.2,110.8) 38.6,110.8 36.5,108.7 36.5,94.5 v1(36,94)
F_LED1: length 15.5
  TOP w0.15: D9.AC26 v1(37,97) ; HL11.2 v1(40.3,108.5)
  MIDLAYER w0.15: v1(37,97) 37,106.3 39.2,108.5 v1(40.3,108.5)
F_LED2: length 15.3
  TOP w0.15: D9.AC24 v1(37,95) ; v1(40.3,106.3) HL12.2
  MIDLAYER w0.15: v1(37,95) 37.5,95.5 37.5,104.6 39.2,106.3 v1(40.3,106.3)
F_LED3: length 10.2
  TOP w0.15: D9.AD26 v1(38,97) ; HL9.2 v1(40.3,104)
  MIDLAYER w0.15: v1(38,97) 38.5,97.5 38.5,102.6 39.9,104 v1(40.3,104)
FPGA_CONDONE: length 176.2
  TOP w0.15: D9.P24 27,95 v1(26,95)
  TOP w0.2: v2(69.2,108.6) 69.8,108.6 70.5,107.9 70.5,106.7 70.8,106.4 R129.1
  MIDLAYER w0.15: v1(40.6,199.9) 40.5,199.9 29.2,188.6 29.2,145.8 24.5,141.1 24.5,108.6 v2(26.2,106.9) 26.5,106.6 26.5,95.5 v1(26,95)
  BOTTOM w0.15: v1(40.6,199.9) 31.3,199.9 29.6,201.6
  BOTTOM w0.2: v2(69.2,108.6) 49.1,108.6 R65.1 35.7,109.7 32.9,106.9 v2(26.2,106.9) ; 29.6,201.6 R121.2
FPGA_DATA0: length 216.4
  TOP w0.15: D9.N7 v1(27,77)
  TOP w0.2: R126.1 71,102.1 67.7,102.1 v2(65.9,100.3)
  MIDLAYER w0.15: v1(27,72) 27.5,71.5 40.21,71.5 52.01,83.3 55.77,83.3 65.9,93.43 v2(65.9,100.3)
  MIDLAYER w0.2: v2(72.5,110.7) 72.1,110.7 65.9,104.5 v2(65.9,100.3)
  BOTTOM w0.15: R136.1 24.4,68.2 27,70.8 v1(27,72) 26.5,72.5 26.5,76.5 v1(27,77)
  BOTTOM w0.2: R124.2 23.6,202.3 29.6,196.3 41.8,196.3 46.8,191.3 46.8,181.9 40.7,175.8 40.7,161.2 55.5,146.4 55.5,136.7 56.3,135.9 65.3,135.9 72.5,128.7 v2(72.5,110.7)
FPGA_DCLK: length 205.5
  TOP w0.15: v1(28,74) D9.P3 v1(28,73)
  TOP w0.2: v2(69.9,107.7) 69.9,106.2 71,105.1 R128.1
  MIDLAYER w0.15: v1(28,74) 28.5,74.5 38.21,74.5 47.4,83.69 v2(47.4,101.1)
  MIDLAYER w0.2: v2(72.5,109.3) 72.4,109.3 70.8,107.7 v2(69.9,107.7)
  BOTTOM w0.15: v1(28,73) 28,69.6 28.7,68.9 R135.1
  BOTTOM w0.2: v2(69.9,107.7) 52.7,107.7 47.4,102.4 v2(47.4,101.1) ; R123.2 27.6,202.5 31.4,198.7 41.4,198.7 47.8,192.3 47.8,179.3 49,178.1 49,161.6 57.7,152.9 66,152.9 74.8,144.1 74.8,111.6 v2(72.5,109.3)
FPGA_INT: length 32.6
  TOP w0.15: D9.AH26 47.3,96.5 51.2,100.4 51.2,116.7 52.75,118.25 D1.45
FPGA_NCONFIG: length 197.7
  TOP w0.15: D9.P4 v1(27,74)
  TOP w0.2: v2(69.2,106.9) 69.2,105.8 71.2,103.8 R127.1
  MIDLAYER w0.15: v1(27,74) 27.5,73.5 37.9,73.5 48.3,83.9 v1(48.3,86.2) v2(48.3,100)
  BOTTOM w0.15: R146.1 C220.1 v1(48.3,86.2)
  BOTTOM w0.2: v2(48.3,100) 48.3,101.8 53.4,106.9 v2(69.2,106.9) 69.88,106.9 71.51,108.53 71.51,117.99 67.9,121.6 67.9,128.19 61.3,134.8 55.52,134.8 51.6,138.72 51.6,145.6 46.1,151.1 42.39,151.1 25.5,167.99 25.5,198.1 21.6,202 R122.2
FPGA_NSTATUS: length 206.4
  TOP w0.15: D9.M6 v1(26,77)
  TOP w0.2: R130.1 71.4,108.3 v2(69.8,109.9)
  MIDLAYER w0.15: v2(69.8,109.9) 69.7,109.8 69.6,109.8 64.1,104.3 64.1,96.1 61.9,93.9 61.9,91.8 61.2,91.1 61.2,89.16 58.94,86.9 52.08,86.9 37.67,72.5 27.3,72.5 26.5,73.3 26.5,76.5 v1(26,77)
  MIDLAYER w0.2: v2(73.4,115.3) 73.4,113.6 69.8,110 v2(69.8,109.9)
  BOTTOM w0.2: R125.2 25.6,202.4 30.5,197.5 41.6,197.5 47.3,191.8 47.3,181.6 42.1,176.4 R64.1 42.1,161.3 54.1,149.3 66.3,149.3 68.9,146.7 68.9,140.2 73.4,135.7 v2(73.4,115.3)
FPGA_TCK: length 26
  TOP w0.15: X7.1 16.83,56.97 28.5,68.64 v1(28.5,70.2) ; D9.P5 v1(28,75)
  BOTTOM w0.15: v1(28,75) 28.5,74.5 v1(28.5,70.2)
  BOTTOM w0.3: X7.1 16.81,56.8 R68.1
FPGA_TDI: length 41.3
  TOP w0.15: X7.9 15.1,48.35 15.1,58.9 26.8,70.6 v1(27.5,70.6) ; D9.P7 v1(28,77)
  BOTTOM w0.15: v1(28,77) 27.5,76.5 v1(27.5,70.6)
  BOTTOM w0.3: X7.9 14.8,48.65 R67.1
FPGA_TDO: length 34
  TOP w0.15: v1(29.5,70.2) 29.5,61.5 21.1,53.1 17.97,53.1 X7.3 ; D9.P6 28,76 v1(30,76)
  BOTTOM w0.15: v1(29.5,70.2) 29.5,75.5 v1(30,76)
FPGA_TMS: length 36.8
  TOP w0.15: v1(29,69.4) 29,62.5 22.1,55.6 v1(18.1,55.6) ; D9.P8 v1(28,78)
  BOTTOM w0.15: v1(28,78) 28,77.8 29,76.8 v1(29,69.4)
  BOTTOM w0.2: v1(18.1,55.6) 18.1,52.97 X7.5
  BOTTOM w0.3: R66.1 X7.5
HS_ADDB_A0: length 130.7
  TOP w0.15: v2(27.4,138.9) 27.1,138.6 27.1,109.9 31,106 31,98 D9.U27
  MIDLAYER w0.15: X1.A19 54.3,212.98 54.3,207.5 31.7,184.9 31.7,143.2 v2(27.4,138.9)
HS_ADDB_A1: length 126.7
  TOP w0.15: v2(28.45,139.15) 27.7,138.4 27.7,110.4 31.5,106.6 D9.V28
  MIDLAYER w0.15: v2(28.45,139.15) 32.2,142.9 32.2,184.9 54.7,207.4 54.7,210.84 X1.B19
HS_ADDB_A2: length 125.1
  TOP w0.15: D9.V27 32,98 32,107.1 28.3,110.8 v2(28.3,138.2)
  MIDLAYER w0.15: v2(28.3,138.2) 32.7,142.6 32.7,184.9 55.82,208.02 X1.C19
HS_ADDB_A3: length 128.7
  TOP w0.15: D9.R28 28.5,105.5 25.6,108.4 25.6,139.5 v2(26.85,140.75)
  MIDLAYER w0.15: X1.A18 51.8,213.02 51.8,208 30.2,186.4 30.2,144.1 v2(26.85,140.75)
HS_ADDB_A4: length 127.1
  TOP w0.15: D9.R27 28.98,97.97 28.98,106.03 26.1,108.9 26.1,139.2 v2(26.55,139.65)
  MIDLAYER w0.15: X1.B18 52.2,210.88 52.2,206.4 30.7,184.9 30.7,143.8 v2(26.55,139.65)
HS_ADDB_A5: length 123.6
  TOP w0.15: v2(27.65,139.95) 26.6,138.9 26.6,109.3 30.5,105.4 D9.U28
  MIDLAYER w0.15: v2(27.65,139.95) 31.2,143.5 31.2,184.9 53.28,206.98 X1.C18
HS_ADDB_A6: length 128.3
  TOP w0.15: D9.M27 25,98 25,107.3 24.5,107.8 24.5,140 v2(26.1,141.6)
  MIDLAYER w0.15: v2(26.1,141.6) 29.5,145 29.5,186.7 49.3,206.5 49.3,213.06 X1.A17
HS_ADDB_A7: length 124.2
  TOP w0.15: v2(25.7,140.4) 25.1,139.8 25.1,108 25.5,107.6 D9.M28
  MIDLAYER w0.15: v2(25.7,140.4) 29.8,144.5 29.8,186.5 49.7,206.4 49.7,210.92 X1.B17
HS_DATB_D0: length 129.4
  TOP w0.15: D9.L26 v1(25,97)
  MIDLAYER w0.15: v1(25,97) 25,105.38 23.1,107.28 23.1,141.8 23.83,142.53 28.3,147 28.3,190 46.7,208.4 46.7,213 X1.A16
HS_DATB_D1: length 127.9
  TOP w0.15: D9.M25 v1(26,96)
  MIDLAYER w0.15: X1.B16 47.1,210.86 47.1,208 28.6,189.5 28.6,146.6 24.45,142.45 23.6,141.6 23.6,107.49 25.5,105.59 25.5,96.5 v1(26,96)
HS_DATB_D2: length 123.9
  TOP w0.15: D9.M26 v1(26,97)
  MIDLAYER w0.15: v1(26,97) 26,105.8 24.1,107.7 24.1,141.4 24.51,141.81 28.9,146.2 28.9,189 48.2,208.3 X1.C16
HS_DATB_D3: length 130.2
  TOP w0.15: D9.K25 v1(24,96)
  MIDLAYER w0.15: X1.A15 44.2,213.04 44.2,208.3 27.4,191.5 27.4,147.9 21.6,142.1 21.6,106.66 23.5,104.76 23.5,96.5 v1(24,96)
HS_DATB_D4: length 126.2
  TOP w0.15: D9.K26 v1(24,97)
  MIDLAYER w0.15: v1(24,97) 24,104.97 22.1,106.87 22.1,142 23.02,142.92 27.7,147.6 27.7,191 44.6,207.9 44.6,210.9 X1.B15
HS_DATB_D5: length 124.7
  TOP w0.15: D9.L25 v1(25,96)
  MIDLAYER w0.15: v1(25,96) 24.5,96.5 24.5,105.18 22.6,107.08 22.6,141.9 23.33,142.63 28,147.3 28,190.5 45.66,208.16 X1.C15
HS_DATB_D6: length 158.6
  TOP w0.15: D9.D25 v1(17,96)
  MIDLAYER w0.15: X1.A14 41.6,212.98 41.6,208.3 37.4,204.1 10,204.1 7.2,201.3 7.2,99 10.7,95.5 16.5,95.5 v1(17,96)
HS_DATB_D7: length 153.7
  TOP w0.15: D9.C25 v1(16,96)
  MIDLAYER w0.15: X1.B14 42,210.84 42,207.8 37.8,203.6 10.3,203.6 7.7,201 7.7,152.9 9.1,151.5 9.1,98.1 11.2,96 v1(16,96)
HS_DATB_D8: length 150.2
  TOP w0.15: D9.C26 v1(16,97)
  MIDLAYER w0.15: X1.C14 43.12,208.02 38.2,203.1 10.6,203.1 8.2,200.7 8.2,153.2 9.6,151.8 9.6,98.6 11.7,96.5 15.5,96.5 v1(16,97)
HS_DATB_D9: length 160.8
  TOP w0.15: D9.D22 v1(17,93)
  MIDLAYER w0.15: v1(17,93) 16.5,93.5 9.9,93.5 6,97.4 6,202.5 9.1,205.6 36.2,205.6 39.1,208.5 39.1,213.02 X1.A13
HS_DATB_D10: length 157.1
  TOP w0.15: D9.D24 v1(17,95)
  MIDLAYER w0.15: X1.B13 39.5,210.88 39.5,208 36.6,205.1 9.4,205.1 6.4,202.1 6.4,97.9 9.8,94.5 16.5,94.5 v1(17,95)
HS_DATB_D11: length 152.3
  TOP w0.15: D9.C24 v1(16,95)
  MIDLAYER w0.15: v1(16,95) 10.2,95 6.8,98.4 6.8,201.7 9.7,204.6 37,204.6 40.58,208.18 X1.C13
HS_DATB_D12: length 147.8
  TOP w0.15: X1.A12 36.6,213.06 36.6,208.5 32.7,204.6 14.1,204.6 6.1,196.6 6.1,101.1 10.7,96.5 D9.A26
HS_DATB_D13: length 158.5
  TOP w0.15: D9.D21 v1(17,92)
  MIDLAYER w0.15: v1(17,92) 16.5,92.5 9.2,92.5 5.2,96.5 5.2,203.3 8.5,206.6 34.2,206.6 36.8,209.2 36.8,210.72 X1.B12
HS_DATB_D14: length 154.1
  TOP w0.15: D9.C22 v1(16,93)
  MIDLAYER w0.15: X1.C12 38.04,208.94 35.2,206.1 8.8,206.1 5.6,202.9 5.6,96.9 9.5,93 v1(16,93)
HS_DATB_D15: length 148.1
  TOP w0.15: X1.A11 34.3,213.3 34.3,208.6 30.8,205.1 13.8,205.1 5.7,197 5.7,100.6 10.3,96 15,96 D9.B26
HS_ENC_RXD: length 146.8
  TOP w0.15: D9.A23 9.9,93.5 4.5,98.9 4.5,199.1 12.6,207.2 24.9,207.2 26.6,208.9 26.6,212.5 27.4,213.3 29.22,213.3 X1.A9
HS_ENC_SCK: length 143.8
  TOP w0.15: D9.B25 15,95 9.4,95 4.9,99.5 4.9,198.5 13,206.6 26.9,206.6 29.2,208.9 29.2,210.74 X1.B9
HS_ENC_TXD: length 149.6
  TOP w0.15: X1.A8 26.58,215.8 25,215.8 24,214.8 24,208.7 23.1,207.8 12.2,207.8 4.1,199.7 4.1,98.6 9.7,93 15,93 D9.B23
HS_FPGA_CS: length 159.5
  TOP w0.15: D9.D20 v1(17,91)
  MIDLAYER w0.15: v1(17,91) 16.5,91.5 8.4,91.5 4.4,95.5 4.4,204.7 7.7,208 30.7,208 31.7,209 31.7,213.24 X1.A10
HS_FPGA_INT: length 167.6
  TOP w0.15: D9.W28 v1(32.5,100) 32.5,107.5 29.4,110.6 v2(29.4,138.4)
  MIDLAYER w0.15: v2(29.4,138.4) 33.1,142.1 33.1,184.8 56.8,208.5 56.8,214.9 56.22,215.47 21.23,215.47 X1.A5
  BOTTOM w0.15: R120.1 v1(32.5,100)
HS_FPGA_RD: length 143.7
  TOP w0.15: D9.A25 9.8,95.5 5.3,100 5.3,197.6 13.5,205.8 29.2,205.8 31.7,208.3 31.7,210.7 X1.B10
HS_FPGA_WR: length 153.5
  TOP w0.15: D9.B21 v1(15,92)
  MIDLAYER w0.15: X1.C11 33.38,207.3 8.1,207.3 4.8,204 4.8,96 8.8,92 v1(15,92)
HS_HPI_HBE1: length 151
  TOP w0.15: D9.E21 v1(18,91)
  TOP w0.2: v2(31,202.4) v2(17.1,202.4)
  BOTTOM w0.15: v2(17.1,202.4) 10.6,202.4 5.5,197.3 5.5,97.8 11.8,91.5 17.5,91.5 v1(18,91)
  BOTTOM w0.2: X1.C10 32.96,204.36 v2(31,202.4)
HS_HPI_HCS: length 153
  TOP w0.15: D9.E22 v1(18,92)
  TOP w0.2: v2(16.1,201.5) 31.2,201.5 v2(32,202.3)
  BOTTOM w0.15: v1(18,92) 17.5,92.5 11.8,92.5 6,98.3 6,196.5 11,201.5 v2(16.1,201.5)
  BOTTOM w0.2: X1.B11 34.3,210.76 34.3,204.6 v2(32,202.3)
HS_HPI_HINT: length 142.9
  TOP w0.15: D9.D19 v1(17,90)
  BOTTOM w0.15: X1.B5 19,210.7 19,205.3 17.8,204.1 9.6,204.1 4.5,199 4.5,96.8 11.8,89.5 16.5,89.5 v1(17,90)
HS_HPI_HRDY: length 138
  TOP w0.15: D9.C19 v1(16,90)
  BOTTOM w0.15: v1(16,90) 12.3,90 4.98,97.32 4.98,198.08 10.2,203.3 18.5,203.3 20.26,205.06 X1.C5
HS_SCL: length 227.2
  TOP w0.15: D9.AH3 44.7,73.5 45.7,72.5 v2(45.7,71.1)
  TOP w0.2: R144.2 79,51.3 v1(78.8,51.1) D33.6 76.8,51.1
  MIDLAYER w0.2: v2(45.7,71.1) 45.7,69.8 64.4,51.1 v2(65.7,51.1)
  BOTTOM w0.2: X1.C31 86.3,202.4 87.8,200.9 87.8,184.2 91.6,180.4 91.6,127 94.9,123.7 94.9,54.6 91.9,51.6 80.7,51.6 80.2,51.1 v1(78.8,51.1) v2(65.7,51.1)
HS_SDA: length 232.7
  TOP w0.15: v2(44.9,70.2) 44.9,72.5 44.4,73 41,73 D9.AG3
  TOP w0.2: R143.2 v1(78.8,49.83) D33.5 76.8,49.83
  MIDLAYER w0.2: v2(63.9,50.5) 44.9,69.5 v2(44.9,70.2)
  BOTTOM w0.2: X1.B31 87.6,210.66 87.6,202 88.4,201.2 88.4,184.4 92.2,180.6 92.2,127.4 95.3,124.3 95.3,54.1 92.2,51 81.4,51 80.23,49.83 v1(78.8,49.83) 64.57,49.83 v2(63.9,50.5)
HS_TS1_CLK: length 25.4
  TOP w0.15: 81.45,193.75 D32.14 ; 81.45,193.75 75.6,199.6 75.6,207.6 74.7,208.5 74.7,213.4 X1.A26 ; 81.45,193.75 81.44,193.75
HS_TS1_D0: length 16.5
  TOP w0.15: X1.A29 82.6,213.12 82.6,206.9 80.4,204.7 80.4,202.3 81.33,201.37 D32.2
HS_TS1_D1: length 14.7
  TOP w0.15: D32.3 81.37,200.73 80,202.1 80,204.8 82.3,207.1 82.3,210.88 X1.B29
HS_TS1_D2: length 13
  TOP w0.15: X1.C29 81.22,206.52 79.7,205 79.7,200.8 81.04,199.46 D32.5
HS_TS1_D3: length 19
  TOP w0.15: X1.A28 79.95,213.22 79.95,205.75 79.4,205.2 79.4,200.38 80.95,198.82 D32.6
HS_TS1_D4: length 17.5
  TOP w0.15: D32.8 81.25,197.56 79.1,199.7 79.1,205.4 79.66,205.96 79.66,210.99 X1.B28
HS_TS1_D5: length 15.1
  TOP w0.15: X1.C28 78.68,199.52 81.28,196.92 D32.9
HS_TS1_D6: length 22.4
  TOP w0.15: D32.11 81.55,195.65 77.6,199.6 77.6,213.04 X1.A27
HS_TS1_D7: length 20.5
  TOP w0.15: X1.B27 77.3,210.8 77.3,199.3 81.58,195.01 D32.12
HS_TS1_VALID: length 18.6
  TOP w0.15: X1.C27 76.14,199.76 81.52,194.38 D32.13
HS_TS2_CLK: length 48.4
  TOP w0.15: X1.A22 64.7,213.24 64.7,208 63.3,206.6 39.2,206.6 32.45,199.84 D31.14
HS_TS2_D0: length 48.7
  TOP w0.15: 40.06,194.1 40.06,200.87 43.1,203.9 67.74,203.9 72.33,208.49 72.33,213.22 X1.A25
HS_TS2_D1: length 46.4
  TOP w0.15: X1.B25 72.03,210.99 72.03,208.62 67.62,204.2 42.6,204.2 39.43,201.03 D31.3
HS_TS2_D2: length 43.5
  TOP w0.15: X1.C25 71.06,208.56 67,204.5 42.2,204.5 38.16,200.46 D31.5
HS_TS2_D3: length 48.7
  TOP w0.15: 37.52,194.1 37.52,200.53 41.8,204.8 66.2,204.8 69.89,208.49 69.89,213.12 X1.A24
HS_TS2_D4: length 46.6
  TOP w0.15: X1.B24 69.59,210.88 69.59,208.62 66.08,205.1 41.4,205.1 36.26,199.96 D31.8
HS_TS2_D5: length 43.2
  TOP w0.15: D31.9 35.62,199.92 41.1,205.4 65.5,205.4 68.52,208.42 X1.C24
HS_TS2_D6: length 48.7
  TOP w0.15: D31.11 34.35,199.35 40.7,205.7 64.66,205.7 67.36,208.39 67.36,213.12 X1.A23
HS_TS2_D7: length 46.4
  TOP w0.15: X1.B23 67.06,210.88 67.06,208.52 64.54,206 40.1,206 33.72,199.62 D31.12
HS_TS2_VALID: length 43.2
  TOP w0.15: X1.C23 65.98,208.18 64.1,206.3 39.7,206.3 33.08,199.68 D31.13
JTAGSEL: length 2.6
  TOP w0.2: D1.105 v2(84.45,114.75)
  BOTTOM w0.3: v2(84.45,114.75) 85.55,114.75 R10.2
KEY0: length 9
  TOP w0.2: R26.2 v2(50.1,135.9) 53.75,132.25 D1.17
  BOTTOM w0.2: v2(50.1,135.9) R26.2
KEY5: length 10.8
  TOP w0.2: D1.24 53.25,128.75 52.2,129.8 52.2,131.8 v2(50.1,133.9) R27.2
  BOTTOM w0.2: R27.2 v2(50.1,133.9)
LED0: length 83.2
  TOP w0.2: D1.121 93.25,122.75 94.1,121.9 94.1,77.3 v1(91.6,74.8) ; v3(74.8,69.7) 72.7,67.6 HL1.2
  MIDLAYER w0.2: v3(74.8,69.7) 78.1,73 89.8,73 v1(91.6,74.8)
LED1: length 85.9
  TOP w0.2: HL2.2 72.1,65.4 v3(74.9,68.2) ; D1.122 93.55,123.25 94.6,122.2 94.6,76.7 v1(91.7,73.8)
  MIDLAYER w0.2: v1(91.7,73.8) 90.4,72.5 79.2,72.5 v3(74.9,68.2)
LED2: length 89.1
  TOP w0.2: v3(74.9,66.6) 71.5,63.2 HL3.2 ; D1.123 93.85,123.75 95.1,122.5 95.1,76.1 v1(92.2,73.2)
  MIDLAYER w0.2: v1(92.2,73.2) 91,72 91,71.98 88.82,69.8 86,69.8 85.35,70.45 78.75,70.45 v3(74.9,66.6)
LED3: length 89.7
  TOP w0.2: D1.124 90.95,124.25 v2(91.1,124.4) ; v3(74.9,65) 70.9,61 HL4.2
  MIDLAYER w0.2: v2(93.6,73.1) 89.6,69.1 85.5,69.1 84.5,70.1 80,70.1 v3(74.9,65)
  BOTTOM w0.2: v2(93.6,73.1) 93.6,123.1 92.3,124.4 v2(91.1,124.4)
LED_100M: length 86.4
  TOP w0.2: D8.13 62.05,91.05 v2(61.9,90.9)
  BOTTOM w0.2: v2(61.9,90.9) 62.3,90.5 62.3,37.1 64.8,34.6 64.8,15.1 68.4,11.5 R53.1
  BOTTOM w0.5: R53.1 69.49,11.49 X6.13
LED_LINK: length 101.3
  TOP w0.2: D8.9 66.25,94.05 65.8,94.5 64.2,94.5 v2(62.9,93.2)
  BOTTOM w0.2: v2(62.9,93.2) 62.9,37.6 66.1,34.4 66.1,17.8 68.95,14.95 79.95,14.95 R58.2
  BOTTOM w0.3: R59.1 R58.2
LOOP0: length 4.8
  TOP w0.15: D9.AH14 v1(41,85)
  BOTTOM w0.15: R72.2 38.9,87 39.15,86.75 39.15,85.95 40.1,85 v1(41,85)
LOOP1: length 6.5
  TOP w0.15: v1(17,85) 16,85 D9.B15
  BOTTOM w0.15: R70.1 20.7,83.3 19,85 v1(17,85)
LOOP2: length 3.8
  TOP w0.15: D9.J2 22,73 v1(22,75)
  BOTTOM w0.15: R73.1 21.8,74.8 v1(22,75)
LOOP3: length 2.7
  TOP w0.15: D9.J27 v1(23,97)
  BOTTOM w0.15: v1(23,97) R71.2
LOOP4: length 2
  TOP w0.15: v1(40,86) D9.AG15
  BOTTOM w0.15: R74.2 v1(40,86)
LOOP5: length 3
  TOP w0.15: D9.B14 v1(15,84)
  BOTTOM w0.15: v1(15,84) 14.4,84.6 R75.2
Net_34: length 0.7
  TOP w0.15: 26.5,95.5 v1(27,96)
Net_35: length 0.7
  TOP w0.15: 26.5,96.5 v1(27,97)
Net_450: length 0.7
  TOP w0.15: 36.5,95.5 v1(37,96)
Net_849: length 1.3
  TOP w0.2: 76.95,112.35 v2(76.95,113.65)
Net_851: length 2.7
  TOP w0.2: 82.45,112.35 82.45,113.65 v3(81.45,114.65)
Net_852: length 4.7
  TOP w0.2: 82.95,112.35 82.95,114.25 v3(80.95,116.25)
Net_853: length 3.8
  TOP w0.2: 83.45,112.35 83.45,114.85 v3(82.55,115.75)
OE1: length 171.6
  TOP w0.15: v2(51.2,79.9) 50.4,79.9 49.8,80.5 D9.AH10 ; D32.48 v1(91.3,202) ; D32.25 v1(90.1,187.4)
  MIDLAYER w0.15: v1(91.3,202) 90.1,200.8 v1(90.1,187.4) 90.1,127.8 85.5,123.2 85.5,95.4 82,91.9 82,82.1 79,79.1 53,79.1 52.2,79.9 v2(51.2,79.9)
  BOTTOM w0.15: R163.1 v1(90.1,187.4)
OE2: length 114.9
  TOP w0.15: D9.Y25 v1(34,96) ; D31.25 v1(26.09,186.19) ; D31.48 v1(40.7,186.5)
  MIDLAYER w0.15: v1(34,96) 35.5,97.5 35.5,108.4 34.3,109.6 34.3,136.8 39.2,141.7 39.2,178.9 40.7,180.4 v1(40.7,186.5)
  BOTTOM w0.15: v1(26.09,186.19) 26.09,186.69 26.6,187.2 37.4,187.2 38.1,186.5 R157.1 v1(40.7,186.5)
PWFBIN: length 8.7
  TOP w0.3: D8.8 v3(66.75,91.15)
  BOTTOM w0.5: 67.25,89.97 66.75,90.47 66.75,90.47 ; 70.65,91.95 C84.1 C83.1 67.13,91.95 C82.1 v3(66.75,91.15) 66.75,90.47 ; 66.75,90.47 L3.2
PWFBOUT: length 7.8
  TOP w0.3: D8.32 v2(68.25,85.35)
  BOTTOM w0.5: 68.27,83.75 68.27,81.03 C81.1 ; 68.27,83.75 68.27,83.75 68.25,83.77 68.25,83.77 ; 68.27,83.75 C80.1 68.25,83.77 ; L3.1 68.25,85.93 68.25,85.93 v2(68.25,85.35) 68.25,83.77
REV: length 229.7
  TOP w0.15: D9.AG4 41,74 45,74 46.4,72.6 v2(46.4,70.8)
  MIDLAYER w0.2: v2(46.4,70.8) 46.4,70.2 v2(64.4,52.2)
  BOTTOM w0.2: X1.A31 85,213.2 85,202.7 87.3,200.4 87.3,183.9 91,180.2 91,126.7 94.5,123.2 94.5,55.1 91.6,52.2 v2(64.4,52.2)
RST8201: length 38.9
  TOP w0.2: v2(69.95,100.2) 69.45,99.7 65.4,99.7 63.6,101.5 63.6,109.5 64.95,110.85 D1.67 ; R43.2 76.55,87.95 v2(75.95,87.95) 75.85,88.05 D8.42
  MIDLAYER w0.2: v2(69.95,100.2) 69.95,97.65 72.55,95.05 72.55,90.85 75.45,87.95 v2(75.95,87.95)
RXD_232: length 96
  TOP w0.2: v2(61.6,56.7) 73.6,44.7 R132.1 ; v2(56.9,105.4) 56.9,113.2 58.3,114.6 64.4,114.6 65.45,113.55 D1.68
  TOP w0.3: R132.1 R131.2
  BOTTOM w0.2: v2(56.9,105.4) 55.6,105.4 54.2,104 54.2,86.5 61,79.7 61,57.3 v2(61.6,56.7)
SCL: length 60.9
  TOP w0.2: v3(88.55,70.9) 88.55,67.3 89.04,66.81 D2.6 ; R5.2 67.4,104.2 67.4,104 ; v2(67.85,103.55) 67.4,104 ; 67.4,104 66.85,104.55 66.85,104.65
  BOTTOM w0.2: R7.1 88.55,70.05 v3(88.55,70.9) 88.55,76.65 82.55,82.65 82.55,93.85 84.95,96.25 84.95,100.15 81.8,103.3 68.1,103.3 v2(67.85,103.55)
SDA: length 63.6
  TOP w0.2: R4.2 64.9,104.6 66.75,102.75 v2(68.8,102.75) ; D2.5 88.91,65.54 87.65,66.8 v3(87.65,71.7)
  BOTTOM w0.2: R6.1 87.65,69.95 v3(87.65,71.7) 87.65,76.25 81.55,82.35 81.55,94.95 84.15,97.55 84.15,99.95 81.35,102.75 v2(68.8,102.75)
TR1: length 173.1
  TOP w0.15: D32.24 v1(86,187.4) ; v1(53.9,80.6) 50.4,80.6 50,81 41,81 D9.AG11
  TOP w0.2: D32.1 v1(84.3,202)
  MIDLAYER w0.15: v1(53.9,80.6) 79.3,80.6 80.7,82 80.7,91.7 85.1,96.1 85.1,123.6 89.8,128.3 89.8,181.5 86,185.3 86,187.39 v1(86,187.4) 86,200.31 v1(84.3,202)
  BOTTOM w0.15: v1(86,187.4) 86,188.69 R161.2
TR2: length 121.4
  TOP w0.15: v1(26.1,192.6) 26.09,192.6 D31.24 ; D9.AB26 v1(36,97)
  TOP w0.2: D31.1 40.7,192.8 41.1,192.4 v1(41.6,192.4)
  MIDLAYER w0.15: v1(41.6,192.4) 41.2,192 41.2,180.2 39.7,178.7 39.7,141.4 34.7,136.4 34.7,110 36,108.7 v1(36,97)
  BOTTOM w0.15: v1(41.6,192.4) 40.8,191.6 26.5,191.6 26.1,192 v1(26.1,192.6)
  BOTTOM w0.2: v1(41.6,192.4) R156.2
TS1_CLK: length 178.7
  TOP w0.15: D32.35 v1(94.5,193.75) ; v1(48.9,73.9) 49.3,73.5 R138.1 ; D9.AE4 v1(38,75)
  MIDLAYER w0.15: v1(48.9,73.9) 49.1,73.7 89.1,73.7 95,79.6 95,189.3 94.5,189.8 v1(94.5,193.75)
  BOTTOM w0.15: v1(38,75) D9.AE4 48.3,74.5 v1(48.9,73.9)
TS1_D0: length 168.8
  TOP w0.15: D9.AG10 41,80 49.6,80 51,78.6 v2(52.1,78.6) ; v1(91.2,201) 91.56,201.37 D32.47
  MIDLAYER w0.15: v1(91.2,201) 90.6,200.4 90.6,127.5 85.9,122.8 85.9,94.8 82.7,91.6 82.7,81.7 79.6,78.6 v2(52.1,78.6)
TS1_D1: length 172.1
  TOP w0.15: D9.AG8 41,78 49.6,78 50.3,77.3 v2(51.5,77.3) ; D32.46 v1(94.07,200.73)
  MIDLAYER w0.15: v1(94.07,200.73) 93.33,200.73 92.2,199.6 92.2,127.5 86.7,122 86.7,82.9 80.6,76.8 71,76.8 70.5,77.3 v2(51.5,77.3)
TS1_D2: length 167.1
  TOP w0.15: v1(91.3,199.1) 91.66,199.46 D32.44 ; D9.AH8 49.9,78.5 50.5,77.9 v2(52.8,77.9)
  MIDLAYER w0.15: v2(52.8,77.9) 70.7,77.9 71.5,77.1 79.6,77.1 86.3,83.8 86.3,122.4 91,127.1 91,198.8 v1(91.3,199.1)
TS1_D3: length 175.3
  TOP w0.15: D9.AH7 49.3,77.5 50.1,76.7 v2(52.7,76.7) ; D32.43 v1(94.1,198.82)
  MIDLAYER w0.15: v2(52.7,76.7) 70.3,76.7 70.5,76.5 89.64,76.5 93.47,80.33 93.47,186.95 92.5,187.92 92.5,197.93 93.4,198.82 v1(94.1,198.82)
TS1_D4: length 175.3
  TOP w0.15: D9.AG7 41,77 49,77 49.9,76.1 v2(51,76.1) ; v1(94.1,197.6) 94.06,197.56 D32.41
  MIDLAYER w0.15: v2(51,76.1) 89.67,76.1 93.78,80.21 93.78,187.17 92.9,188.05 92.9,196.7 93.8,197.6 v1(94.1,197.6)
TS1_D5: length 174.6
  TOP w0.15: D32.40 v1(94.5,196.92) ; D9.AH6 48.7,76.5 49.7,75.5 v2(52.7,75.5)
  MIDLAYER w0.15: v2(52.7,75.5) 89.49,75.5 94.08,80.08 94.08,187.67 93.3,188.44 93.3,196.2 94.02,196.92 v1(94.5,196.92)
TS1_D6: length 174.2
  TOP w0.15: D32.38 v1(94.15,195.65) ; v2(51.3,74.9) 49.6,74.9 48.5,76 41,76 D9.AG6
  MIDLAYER w0.15: v1(94.15,195.65) 93.7,195.2 93.7,188.94 94.38,188.26 94.38,79.96 89.31,74.9 v2(51.3,74.9)
TS1_D7: length 173
  TOP w0.15: v2(52.7,74.3) 49.6,74.3 49.4,74.5 D9.AH4 ; D32.37 v1(94.52,195.01)
  MIDLAYER w0.15: v1(94.52,195.01) 94,194.5 94,189.3 94.67,188.62 94.67,79.83 89.14,74.3 v2(52.7,74.3)
TS1_VALID: length 177.6
  TOP w0.15: D32.36 v1(95.1,194.38) ; D9.AF4 v1(40,74) ; R141.1 47.9,72.9 v1(48.4,73.4)
  MIDLAYER w0.15: v1(48.4,73.4) 89.3,73.4 95.3,79.4 95.3,189.7 95.1,189.9 v1(95.1,194.38)
  BOTTOM w0.15: v1(48.4,73.4) 47.8,74 v1(40,74)
TS2_CLK: length 93.8
  TOP w0.15: D9.F26 20,97 v1(20,100.6) 20,141.5 27.1,148.6 27.1,173.7 32.45,179.04 D31.35
  BOTTOM w0.15: R137.1 v1(20,100.6)
TS2_D0: length 91
  TOP w0.15: D9.Y26 v1(34,97) ; 40.06,184.19 v1(40.06,181.8)
  MIDLAYER w0.15: v1(34,97) 34.5,97.5 34.5,108.6 33.8,109.3 33.8,137.1 34.35,137.65 34.35,174.95 40.06,180.66 v1(40.06,181.8)
TS2_D1: length 92.7
  TOP w0.15: D9.Y24 v1(34,95) ; D31.46 v1(39.43,182.6)
  MIDLAYER w0.15: v1(39.43,182.6) 39.43,180.93 33.73,175.23 33.73,137.83 33.3,137.4 33.3,109 33.5,108.8 33.5,95.5 v1(34,95)
TS2_D2: length 91.8
  TOP w0.15: D9.L28 24.5,106.9 24,107.4 24,140.8 29.9,146.7 29.9,170.3 38.16,178.56 D31.44
TS2_D3: length 92.9
  TOP w0.15: D9.L27 24,98 24,106.5 23.5,107 23.5,141 29.5,147 29.5,170.8 37.52,178.82 37.52,184.19
TS2_D4: length 91.4
  TOP w0.15: D9.K28 23.5,106.2 23,106.7 23,141.1 29.1,147.2 29.1,171.8 36.26,178.96 D31.41
TS2_D5: length 92.5
  TOP w0.15: D31.40 35.62,179.22 28.7,172.3 28.7,147.4 22.5,141.2 22.5,106.3 23,105.8 23,98 D9.K27
